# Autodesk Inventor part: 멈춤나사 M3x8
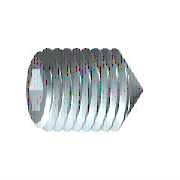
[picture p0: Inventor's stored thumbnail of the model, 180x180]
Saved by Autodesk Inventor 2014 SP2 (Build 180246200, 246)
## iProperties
IsCustomPart: 1
Created: 2012-02
Part Number: 멈춤나사 M3x8
Material: 강철, 연강
Description: 6각 소켓 머리 없는 멈춤 나사
Document SubType Name: Modeling
Standard: KS B 1028
Designer: test
Standards Organization: KS
Language: ko-KR
Size Designation: 원추점 M3x8
Categories: <MemberInstance><Categories><Category DisplayName="조임쇠" InternalName="e4da775c-781d-43d5-af7c-5136215cf5a6" Mnemonic="FSTN"><Category DisplayName="볼트" InternalN
Density: 1 g/cm^3
Appearance: 강철
Author: test
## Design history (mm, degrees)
sketch "스케치1"
  geometry: L1 (0, 0)-(5.5, 0); L2 (8, 0.866)-(8, 1.5); L3 (8, 1.5)-(0, 1.5); L4 (8, 0.866)-(6, 0.866); L5 (6, 0.866)-(5.5, 0); L6 (0, -0.3)-(0, 1.8) reference; L7 (0, 1.5)-(0, 0)
  constraints: 13 end point, 3 parallel, 1 collinear, 1 perpendicular, 1 point on line
  dimensions: "d0" = 2 distance of L2.start L4.end (= INTI); "d1" = 60 deg angle of L5 L1; "d2" = 3 diameter of L3 L1 (= NND); "d3" = 1.73205 diameter of L4 L1 (= 1.1547 x SW); "d5" = 8 distance from line of L2 L3.end (= NLG)
revolve "본체" sketch "스케치1" stored, may be unused: angle "d6" = 90 deg
sketch "스케치2"
  geometry: L1 (-0.433, 0.75)-(0.433, 0.75); L2 (0.433, 0.75)-(0.866, 0); L3 (0.866, 0)-(0.433, -0.75); L4 (0.433, -0.75)-(-0.433, -0.75); L5 (-0.433, -0.75)-(-0.866, 0); L6 (-0.866, 0)-(-0.433, 0.75); 3 further points
  constraints: 12 end point, 1 coincident, 1 horizontal, 13 other
extrude "슬롯" join sketch "스케치2" taper "d7" = 0 deg; stored distance "d21" = 10
workaxis "Work Axis1"
workplane "Work Plane1"
sketch "스케치4"
  geometry: L1 (0, 0.15)-(-1.35, 1.5) reference; L2 (0, -0.15)-(-1.35, -1.5) reference; L3 (-1.35, -1.5)-(0.15, 0); L4 (-1.35, 1.5)-(0.15, 0); 2 further points
  constraints: 4 end point, 1 coincident, 1 collinear, 1 horizontal alignment
body "Solid1"
feature "스레드" dims "d12" = 8 (= NLG), "d13" = 0
chamfer "모따기1" distance "d8" = 1.35 (computed from NND, SPD, FAWI); stored, may be unused: angle "d9" = 45 deg (= FAWI), second distance "d34" = 1.35 (computed from NND, SPD, FAWI)
chamfer "모따기2" distance "d10" = 0.30673 (= -0.5 x GD1 + 0.5 x NND); stored, may be unused: angle "d11" = 45 deg (= FAWI), second distance "d35" = 0.30673 (= -0.5 x GD1 + 0.5 x NND)
other parameters: "NND" = 3 [user parameter; used in 5 equation terms], "NLG" = 8 [user parameter; used in 2 equation terms], "INTI" = 2 [user parameter; used in 1 equation term], "FAWI" = 45 deg [user parameter; used in 4 equation terms], "SW" = 1.5 [user parameter; used in 2 equation terms], "GD1" = 2.38655 (= THREADDIA - 1.2269 x PTC) [user parameter; used in 2 equation terms], "d4" = 0, "FAWI1" = 45 deg [user parameter], "SPD" = 0.3 [user parameter; used in 2 equation terms], "d36" = 0, "d37" = 0, "GUL" = 0.30673 (= 0.61345 x PTC) [user parameter], "TOA" = 30 deg [user parameter], "THREADDIA" = 3 [user parameter; used in 1 equation term], "PTC" = 0.5 [user parameter; used in 4 equation terms], "GAL" = 0.30673 (= 0.61345 x PTC) [user parameter], "E0" = 1.7325 (= 1.155 x SW) [user parameter]
